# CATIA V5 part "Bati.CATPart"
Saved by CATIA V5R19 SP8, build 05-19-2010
Part number: Bati
Bounding box of the stored display mesh (mm): x 50 to 150, y -60 to 185, z -230 to 30
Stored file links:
  C:\Users\ThinkMotion\Desktop\EU_thinkMotion\iao\IAO_MMS_Groupe3\rdalborgo\rdalborgo\Bati.CATPart
  C:\Users\ThinkMotion\Desktop\EU_thinkMotion\iao\IAO_MMS_Groupe3\rdalborgo\rdalborgo\rdalborgo.CATProduct
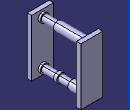
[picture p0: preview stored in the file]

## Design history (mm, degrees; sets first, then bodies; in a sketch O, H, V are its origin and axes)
External parameters (linked from other documents)
  `External.Hauteur bati` = 200 mm
  `External.Axe inter diam` = 30 mm
  `External.Deport bielle bati` = 165 mm
  `External.Demi epaisseur tete bielle` = 30 mm
Set1
  Plane1: linked copy from another document
  Point1 "A bati": linked copy from another document
  Line1: linked copy from another document
  Line2: linked copy from another document
  Point2 "Origine": linked copy from another document
  Line3: linked copy from another document
  Point3 "D verin": linked copy from another document
  Point4 "A bielle": linked copy from another document
Body1 (main body)
  Sketch1 on Plane1, origin (100, 0, 0), H (0, 1, 0), V (0, 0, 1)
    line L1 (165, 30) -> (185, 30)
    line L2 (185, 30) -> (185, -230)
    line L3 (185, -230) -> (165, -230)
    line L4 (165, -230) -> (165, 30)
    reference projected point E1 (165, 0) from Point1
    reference projected line E2 (165, 0) -> (165, -200) from Line1
    distance L1 L3 = 260 {= `External.Hauteur bati` +60mm}
    distance L1 E1 = 30
    distance L2 L4 = 20
    horizontal: L1 H, L3 H
    vertical: L2 V, L4 V
    coincidence: L4 E2
  Pad1: profile Sketch1, direction (1, 0, 0), length 50, mirrored extent
  Sketch2 on Plane1, origin (100, 0, 0), H (0, 1, 0), V (0, 0, 1)
    line L1 (165, 20) -> (30, 20)
    line L2 (30, 20) -> (30, 15)
    line L3 (30, 15) -> (-30, 15)
    line L4 (-30, 15) -> (-30, 20)
    point P5 (-30, 20)
    line L5 (-30, 20) -> (-40, 20)
    line L6 (-40, 20) -> (-40, 0)
    line L7 (-40, 0) -> (165, 0)
    line L8 (165, 0) -> (165, 20)
    reference projected line E1 (120, 0) -> (160, 0) from Line2
    reference projected line E2 (165, 0) -> (165, -200) from Line1
    reference projected point E3 (0, 0) from Point2
    distance L1 L7 = 20 {= (`External.Axe inter diam` +10mm)/2}
    distance L3 L7 = 15 {= `External.Axe inter diam` /2}
    distance L8 L6 = 205 {= `External.Deport bielle bati` +40mm}
    distance L4 L2 = 60 {= `External.Demi epaisseur tete bielle` *2}
    distance L2 E3 = 30 {= `External.Demi epaisseur tete bielle`}
    horizontal: L1 H, L3 H, L5 H, L7 H
    vertical: L2 V, L4 V, L6 V, L8 V
    coincidence: P5 L1, L7 E1, L8 E2, L5 L1
  Shaft1: profile Sketch2, axis Line2, angle 360
  Sketch3 on Plane1, origin (100, 0, 0), H (0, 1, 0), V (0, 0, 1)
    line L1 (165, -200) -> (165, -180)
    line L2 (165, -180) -> (95, -180)
    line L3 (95, -180) -> (95, -185)
    line L4 (95, -185) -> (45, -185)
    line L5 (45, -185) -> (45, -180)
    point P6 (45, -180)
    line L6 (45, -180) -> (30, -180)
    line L7 (30, -180) -> (30, -185)
    line L8 (30, -185) -> (-30, -185)
    line L9 (-30, -185) -> (-30, -180)
    line L10 (-30, -180) -> (-40, -180)
    line L11 (-40, -180) -> (-40, -200)
    line L12 (-40, -200) -> (165, -200)
    reference projected line E1 (165, 0) -> (165, -200) from Line1
    reference projected line E2 (120, -200) -> (160, -200) from Line3
    reference projected point E3 (0, 0) from Point2
    reference projected point E4 (70, -200) from Point3
    distance L1 L11 = 205 {= `External.Deport bielle bati` +40mm}
    distance L2 L12 = 20 {= (`External.Axe inter diam` +10mm)/2}
    distance L4 L12 = 15 {= `External.Axe inter diam` /2}
    distance L9 L7 = 60 {= `External.Demi epaisseur tete bielle` *2}
    distance L7 E3 = 30 {= `External.Demi epaisseur tete bielle`}
    distance L3 L5 = 50
    distance L5 E4 = 25
    vertical: L1 V, L3 V, L5 V, L7 V, L9 V, L11 V
    horizontal: L2 H, L4 H, L6 H, L8 H, L10 H, L12 H
    coincidence: P6 L2, L1 E1, L12 E2, L10 L6, L2 L6, L8 L4
  Shaft2: profile Sketch3, axis Line3, angle 360
  Sketch4 on face of Shaft2 from Sketch3.L11, origin (0, -40, 0), H (1, 0, 0), V (0, 0, 1)
    line L1 (50, 30) -> (150, 30)
    line L2 (150, 30) -> (150, -230)
    line L3 (150, -230) -> (50, -230)
    line L4 (50, -230) -> (50, 30)
    reference projected point E1 (100, 0) from Point1
    reference projected point E2 (100, 0) from Point1
    reference projected point E3 (100, 0) from Point1
    reference projected point E4 (100, 0) from Point4
    distance L1 L3 = 260 {= `External.Hauteur bati` +60mm}
    distance E1 E2 = 0 (reference)
    distance L1 E3 = 30
    distance L4 L2 = 100
    distance L4 E4 = 50
    horizontal: L1 H, L3 H
    vertical: L2 V, L4 V
  Pad2: profile Sketch4, direction (0, -1, 0), length 20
